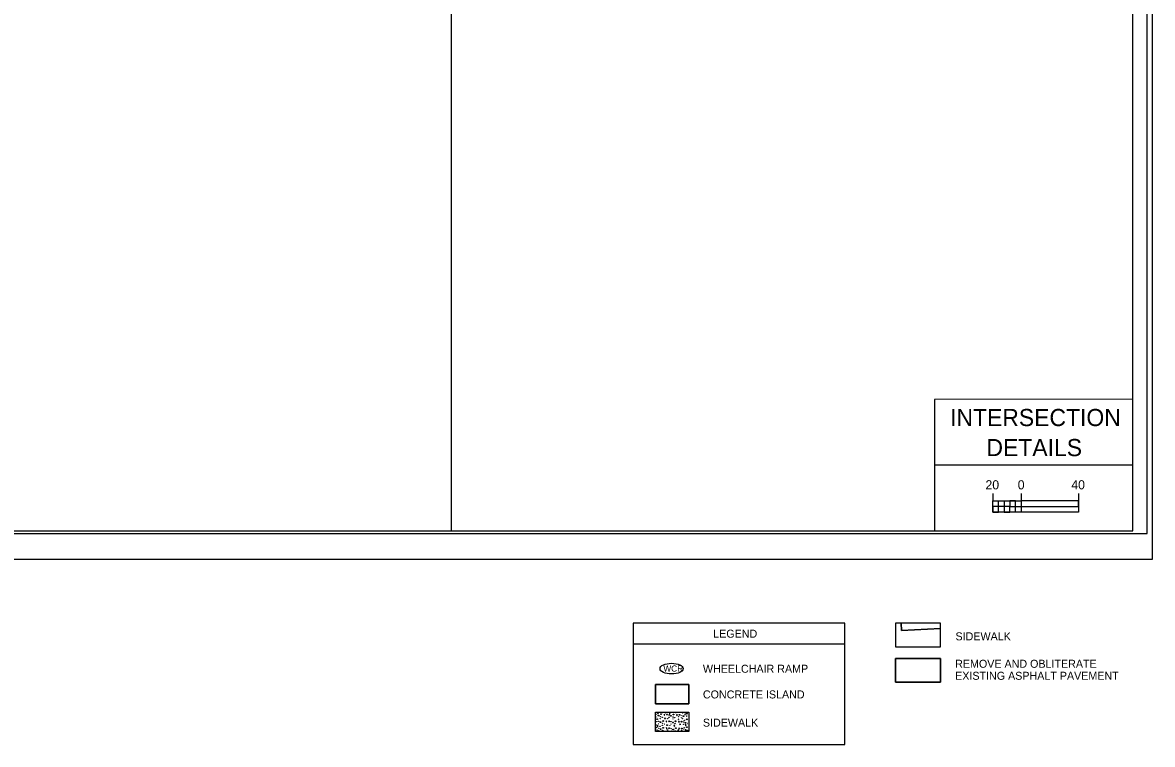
# Model space of a CAD drawing. Extents: x 2431000 to 2534000, y 645879 to 714000.
# Drawn here: x 2467604 to 2468592, y 661112 to 661743 of the extents above; entities that cross this region are included whole.
import ezdxf

# ---------------------------------------------------------------- set-up
doc = ezdxf.new("R2010")
doc.units = 0
for name, color, linetype in [('Default', 7, 'Continuous'), ('Level 25', 7, 'Continuous'), ('Old_Level_1', 7, 'Continuous'), ('Old_Level_40', 7, 'Continuous'), ('Prop DSN Text', 7, 'Continuous'), ('Prop Rem of Exist Asph Pvmt', 7, 'Continuous'), ('Prop Shade Light', 7, 'Continuous'), ('Prop WCC CELL', 7, 'Continuous'), ('Sheet Plan CELL', 7, 'Continuous'), ('Sheet Plot Border Inside CELL', 7, 'Continuous'), ('Sheet Plot Border Outside CELL', 7, 'Continuous'), ('Sheet Typical CELL', 7, 'Continuous')]:
    doc.layers.add(name, color=color, linetype=linetype)

msp = doc.modelspace()

# ---------------------------------------------------------------- linework, layer by layer
at = {"layer": 'Level 25'}
msp.add_lwpolyline([(2468157.55, 661164.11), (2468157.55, 661147.27), (2468186.74, 661147.27), (2468186.74, 661164.11), (2468157.55, 661164.11)], dxfattribs=at)
for points in [[(2468165.89, 661137.65), (2468165.14, 661138.25), (2468165.32, 661137.22)], [(2468170.54, 661138.53), (2468169.79, 661139.13), (2468169.97, 661138.1)], [(2468176.82, 661137.36), (2468176.07, 661137.96), (2468176.25, 661136.93)], [(2468183.97, 661137.93), (2468183.22, 661138.53), (2468183.4, 661137.5)], [(2468159.99, 661127.71), (2468159.25, 661128.31), (2468159.42, 661127.28)], [(2468167.69, 661131.76), (2468166.95, 661132.36), (2468167.12, 661131.33)], [(2468167.85, 661125.74), (2468167.11, 661126.34), (2468167.28, 661125.31)], [(2468174.59, 661127.87), (2468173.84, 661128.47), (2468174.02, 661127.44)], [(2468178.62, 661131.47), (2468177.88, 661132.07), (2468178.05, 661131.04)], [(2468178.79, 661125.46), (2468178.04, 661126.06), (2468178.21, 661125.03)], [(2468184.41, 661128.43), (2468183.66, 661129.03), (2468183.84, 661128)], [(2468177.95, 661123.94), (2468177.21, 661124.54), (2468177.38, 661123.51)]]:
    msp.add_lwpolyline(points, close=True, dxfattribs=at)
for centre, radius in [((2468158.57, 661137.75), 0.131), ((2468158.57, 661135.58), 0.131), ((2468159.78, 661139.06), 0.356), ((2468160.25, 661136.97), 0.356), ((2468161.98, 661135.96), 0.131), ((2468162.5, 661138.09), 0.356), ((2468163.73, 661139.5), 0.131), ((2468166.7, 661139.34), 0.131), ((2468167.75, 661137.77), 0.356), ((2468169.5, 661137.46), 0.131), ((2468171.18, 661136.69), 0.356), ((2468172.91, 661135.67), 0.131), ((2468173.44, 661137.8), 0.356), ((2468174.96, 661139.34), 0.131), ((2468177.76, 661135.98), 0.131), ((2468178.69, 661137.48), 0.356), ((2468180.44, 661137.18), 0.131), ((2468181.25, 661139.06), 0.131), ((2468182.12, 661136.4), 0.356), ((2468185.19, 661138.61), 0.356), ((2468185.06, 661136.42), 0.131), ((2468158.21, 661126.43), 0.356), ((2468158.68, 661131.49), 0.131), ((2468158.68, 661128.56), 0.131), ((2468159.1, 661133.72), 0.356), ((2468160.37, 661131.86), 0.131), ((2468160.38, 661129.69), 0.131), ((2468160.53, 661125.84), 0.131), ((2468161.61, 661127.56), 0.131), ((2468162.05, 661131.08), 0.356), ((2468161.88, 661134.32), 0.131), ((2468163.6, 661135.28), 0.131), ((2468163.68, 661128.43), 0.131), ((2468163.78, 661130.07), 0.131), ((2468164.31, 661132.19), 0.356), ((2468164.47, 661126.18), 0.356), ((2468165.41, 661129.38), 0.131), ((2468165.98, 661134.42), 0.356), ((2468167.79, 661128.53), 0.356), ((2468168.42, 661134.15), 0.131), ((2468169.56, 661131.88), 0.356), ((2468169.72, 661125.87), 0.356), ((2468169.51, 661135.3), 0.131), ((2468170.23, 661128.26), 0.131), ((2468171.31, 661131.57), 0.131), ((2468171.31, 661129.4), 0.131), ((2468171.47, 661125.56), 0.131), ((2468172.99, 661130.79), 0.356), ((2468172.87, 661134.05), 0.131), ((2468174.54, 661134.99), 0.131), ((2468174.72, 661129.78), 0.131), ((2468175.24, 661131.91), 0.356), ((2468175.4, 661125.89), 0.356), ((2468176.34, 661129.09), 0.131), ((2468177.76, 661133.73), 0.131), ((2468179.14, 661129.23), 0.356), ((2468180.49, 661131.59), 0.356), ((2468180.65, 661125.58), 0.356), ((2468180.44, 661135.01), 0.131), ((2468181.13, 661134.17), 0.131), ((2468182.24, 661131.28), 0.131), ((2468182.24, 661129.11), 0.131), ((2468182.82, 661132.77), 0.131), ((2468182.82, 661126.44), 0.131), ((2468183.92, 661130.51), 0.356), ((2468185.03, 661126.71), 0.356), ((2468185.15, 661133.6), 0.356), ((2468185.46, 661129.96), 0.131), ((2468158.96, 661124.35), 0.131), ((2468160.54, 661123.68), 0.131), ((2468162.21, 661125.07), 0.356), ((2468163.94, 661124.06), 0.131), ((2468165.57, 661123.37), 0.131), ((2468168.27, 661124.22), 0.131), ((2468171.47, 661123.39), 0.131), ((2468173.15, 661124.78), 0.356), ((2468174.88, 661123.77), 0.131), ((2468180.54, 661123.9), 0.356), ((2468182.4, 661125.27), 0.131), ((2468184.08, 661124.49), 0.356), ((2468185.62, 661124.07), 0.131)]:
    msp.add_circle(centre, radius, dxfattribs=at)
at = {"layer": 'Old_Level_1'}
msp.add_lwpolyline([(2468367.68, 661217.81), (2468367.68, 661197.04), (2468406.84, 661197.04), (2468406.84, 661217.81), (2468367.68, 661217.81)], dxfattribs=at)
for points in [[(2468367.68, 661186.73), (2468406.84, 661186.73), (2468406.84, 661165.96), (2468367.68, 661165.96)], [(2468157.55, 661164.11), (2468186.74, 661164.11), (2468186.74, 661147.27), (2468157.55, 661147.27)], [(2468157.55, 661139.89), (2468186.74, 661139.89), (2468186.74, 661123.05), (2468157.55, 661123.05)]]:
    msp.add_lwpolyline(points, close=True, dxfattribs=at)
at = {"layer": 'Old_Level_40'}
for p, q in [((2468452.56, 661330.93), (2468452.56, 661324.68)), ((2468477.56, 661330.93), (2468477.56, 661324.68))]:
    msp.add_line(p, q, dxfattribs=at)
msp.add_lwpolyline([(2468527.56, 661330.93), (2468527.56, 661314.68), (2468452.56, 661314.68), (2468452.56, 661324.68), (2468477.56, 661324.68)], dxfattribs=at)
for points in [[(2468462.56, 661319.68), (2468457.56, 661319.68), (2468457.56, 661324.68), (2468462.56, 661324.68)], [(2468472.56, 661324.68), (2468467.56, 661324.68), (2468467.56, 661319.68), (2468472.56, 661319.68)], [(2468527.56, 661324.68), (2468477.56, 661324.68), (2468477.56, 661319.68), (2468527.56, 661319.68)], [(2468457.56, 661319.68), (2468452.56, 661319.68), (2468452.56, 661314.68), (2468457.56, 661314.68)], [(2468467.56, 661319.68), (2468462.56, 661319.68), (2468462.56, 661314.68), (2468467.56, 661314.68)], [(2468477.56, 661314.68), (2468472.56, 661314.68), (2468472.56, 661319.68), (2468477.56, 661319.68)]]:
    msp.add_lwpolyline(points, close=True, dxfattribs=at)
at = {"layer": 'Prop Rem of Exist Asph Pvmt'}
msp.add_lwpolyline([(2468367.68, 661186.73), (2468367.68, 661165.96), (2468406.84, 661165.96), (2468406.84, 661186.73), (2468367.68, 661186.73)], dxfattribs=at)
at = {"layer": 'Prop Shade Light'}
for p, q in [((2468372.82, 661211.21), (2468372.48, 661217.81)), ((2468406.84, 661217.81), (2468372.48, 661217.81)), ((2468372.48, 661217.81), (2468372.82, 661211.21)), ((2468406.84, 661212.91), (2468406.84, 661217.81)), ((2468406.84, 661212.91), (2468372.82, 661211.21)), ((2468372.82, 661211.21), (2468406.84, 661212.91))]:
    msp.add_line(p, q, dxfattribs=at)
msp.add_lwpolyline([(2468372.48, 661217.81), (2468367.68, 661217.81), (2468367.68, 661197.04), (2468406.84, 661197.04), (2468406.84, 661212.91)], dxfattribs=at)
at = {"layer": 'Prop WCC CELL'}
msp.add_ellipse((2468171.73, 661177.94), major_axis=(10.09, 0), ratio=0.462467, dxfattribs=at)
at = {"layer": 'Sheet Plan CELL'}
msp.add_line((2468138.13, 661199.49), (2468323.18, 661199.49), dxfattribs=at)
for points in [[(2468575.2, 661413.32), (2468401.64, 661413.27), (2468401.66, 661355.84)], [(2468575.22, 661355.89), (2468401.66, 661355.84), (2468401.67, 661298.4)]]:
    msp.add_lwpolyline(points, dxfattribs=at)
msp.add_lwpolyline([(2468323.18, 661217.81), (2468138.13, 661217.81), (2468138.13, 661111.71), (2468323.18, 661111.71)], close=True, dxfattribs=at)
at = {"layer": 'Sheet Plot Border Inside CELL'}
msp.add_lwpolyline([(2466921.74, 661295.96), (2468587.74, 661295.96), (2468587.74, 662350.96), (2466921.74, 662350.96)], close=True, dxfattribs=at)
at = {"layer": 'Sheet Plot Border Outside CELL'}
msp.add_lwpolyline([(2466908.74, 661273.46), (2468592.24, 661273.46), (2468592.24, 662373.46), (2466908.74, 662373.46)], close=True, dxfattribs=at)
at = {"layer": 'Sheet Typical CELL'}
msp.add_line((2467978.88, 661823.46), (2467978.88, 661298.46), dxfattribs=at)
msp.add_lwpolyline([(2468575.24, 662348.46), (2467075.24, 662348.46), (2467075.24, 661298.46), (2468575.24, 661298.46)], close=True, dxfattribs=at)

# ---------------------------------------------------------------- texts
at = {"layer": 'Default'}
for s, p in [('LEGEND', (2468208.16, 661204.98)), ('REMOVE AND OBLITERATE', (2468419.73, 661178.68)), ('EXISTING ASPHALT PAVEMENT', (2468419.73, 661168.18))]:
    msp.add_text(s, height=7, dxfattribs=at).set_placement(p)
for s, rotation, p in [('SIDEWALK', 0.01753, (2468420.04, 661202.64)), ('WHEELCHAIR RAMP', 359.99994, (2468199.14, 661174.33)), ('CONCRETE ISLAND', 359.99994, (2468199.14, 661151.88)), ('SIDEWALK', 359.99994, (2468199.14, 661127.19))]:
    msp.add_text(s, height=7, rotation=rotation, dxfattribs=at).set_placement(p)
at = {"layer": 'Old_Level_40'}
for s, p in [('20', (2468446.28, 661334.6)), ('0', (2468474.48, 661334.6)), ('40', (2468521.32, 661334.6))]:
    msp.add_text(s, height=8, dxfattribs=at).set_placement(p)
at = {"layer": 'Prop DSN Text'}
for s, p in [('INTERSECTION', (2468415.28, 661389.91)), ('DETAILS', (2468447.11, 661363.66))]:
    msp.add_text(s, height=15, rotation=360, dxfattribs=at).set_placement(p)
at = {"layer": 'Prop WCC CELL'}
msp.add_text('WCR', height=5.4, dxfattribs=at).set_placement((2468164.6, 661175.28))

doc.saveas('drawing.dxf')
